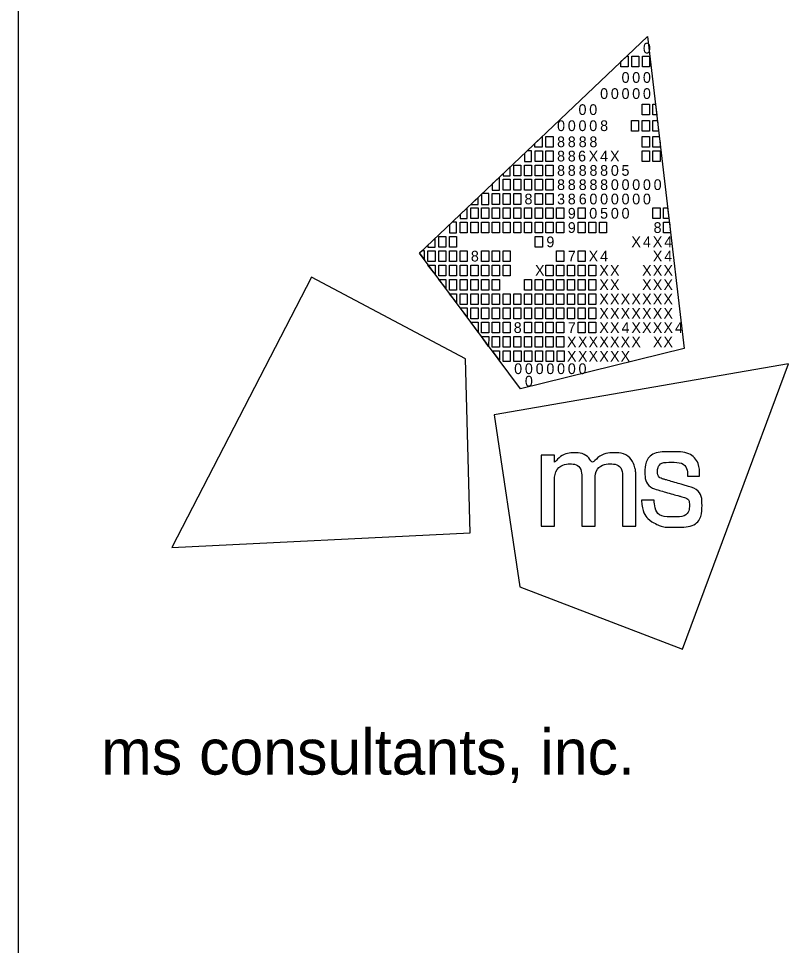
# Model space of a CAD drawing. Extents: x 0 to 34, y 0 to 22.
# Drawn here: x 32 to 33.186, y 2.686 to 4.114 of the extents above; entities that cross this region are included whole.
import ezdxf

# ---------------------------------------------------------------- set-up
doc = ezdxf.new("R2010")
doc.units = 0
doc.layers.add('SH_Border', color=7, linetype='Continuous')
doc.layers.add('SH_Data', color=7, linetype='Continuous')

msp = doc.modelspace()

# ---------------------------------------------------------------- linework, layer by layer
at = {"layer": 'SH_Border'}
msp.add_line((32, 0.5), (32, 21.5), dxfattribs=at)
at = {"layer": 'SH_Data'}
for p, q in [((32.6175, 3.7519), (32.9688, 4.0861)), ((32.9688, 4.0861), (32.9688, 4.0861)), ((32.9688, 4.0861), (33.0253, 3.6052)), ((32.773, 3.543), (32.6175, 3.7519)), ((33.0253, 3.6052), (32.773, 3.543)), ((32.75, 3.5), (32.75, 3.5))]:
    msp.add_line(p, q, dxfattribs=at)
for points in [[(32.9279, 4.0472), (32.9369, 4.0558), (32.9389, 4.0558), (32.9389, 4.0393), (32.9279, 4.0393)], [(32.9444, 4.0558), (32.9554, 4.0558), (32.9554, 4.0393), (32.9444, 4.0393)], [(32.9609, 4.0558), (32.9719, 4.0558), (32.9719, 4.0393), (32.9609, 4.0393)], [(32.9606, 3.9815), (32.9716, 3.9815), (32.9716, 3.965), (32.9606, 3.965)], [(32.9771, 3.9815), (32.9811, 3.9815), (32.983, 3.965), (32.9771, 3.965)], [(32.9441, 3.9567), (32.9551, 3.9567), (32.9551, 3.9402), (32.9441, 3.9402)], [(32.9606, 3.9567), (32.9716, 3.9567), (32.9716, 3.9402), (32.9606, 3.9402)], [(32.9771, 3.9567), (32.984, 3.9567), (32.9859, 3.9402), (32.9771, 3.9402)], [(32.7953, 3.9211), (32.8064, 3.9316), (32.8064, 3.9154), (32.7953, 3.9154)], [(32.8123, 3.9319), (32.8233, 3.9319), (32.8233, 3.9154), (32.8123, 3.9154)], [(32.9606, 3.9319), (32.9716, 3.9319), (32.9716, 3.9154), (32.9606, 3.9154)], [(32.9771, 3.9319), (32.9869, 3.9319), (32.9881, 3.9218), (32.9881, 3.9154), (32.9771, 3.9154)], [(32.7958, 3.9099), (32.8068, 3.9099), (32.8068, 3.8934), (32.7958, 3.8934)], [(32.8123, 3.9099), (32.8233, 3.9099), (32.8233, 3.8934), (32.8123, 3.8934)], [(32.9606, 3.9099), (32.9716, 3.9099), (32.9716, 3.8934), (32.9606, 3.8934)], [(32.9771, 3.9099), (32.9881, 3.9099), (32.9881, 3.8934), (32.9771, 3.8934)], [(32.7627, 3.8879), (32.7737, 3.8879), (32.7737, 3.8714), (32.7627, 3.8714)], [(32.7793, 3.8879), (32.7903, 3.8879), (32.7903, 3.8714), (32.7793, 3.8714)], [(32.7958, 3.8879), (32.8068, 3.8879), (32.8068, 3.8714), (32.7958, 3.8714)], [(32.8123, 3.8879), (32.8233, 3.8879), (32.8233, 3.8714), (32.8123, 3.8714)], [(32.7462, 3.8659), (32.7572, 3.8659), (32.7572, 3.8494), (32.7462, 3.8494)], [(32.7627, 3.8659), (32.7737, 3.8659), (32.7737, 3.8494), (32.7627, 3.8494)], [(32.7793, 3.8659), (32.7903, 3.8659), (32.7903, 3.8494), (32.7793, 3.8494)], [(32.7958, 3.8659), (32.8068, 3.8659), (32.8068, 3.8494), (32.7958, 3.8494)], [(32.8123, 3.8659), (32.8233, 3.8659), (32.8233, 3.8494), (32.8123, 3.8494)], [(32.7297, 3.8439), (32.7407, 3.8439), (32.7407, 3.8273), (32.7297, 3.8273)], [(32.7462, 3.8439), (32.7572, 3.8439), (32.7572, 3.8273), (32.7462, 3.8273)], [(32.7627, 3.8439), (32.7737, 3.8439), (32.7737, 3.8273), (32.7627, 3.8273)], [(32.7958, 3.8439), (32.8068, 3.8439), (32.8068, 3.8273), (32.7958, 3.8273)], [(32.8123, 3.8439), (32.8233, 3.8439), (32.8233, 3.8273), (32.8123, 3.8273)], [(32.6967, 3.8218), (32.7077, 3.8218), (32.7077, 3.8053), (32.6967, 3.8053)], [(32.7132, 3.8218), (32.7242, 3.8218), (32.7242, 3.8053), (32.7132, 3.8053)], [(32.7297, 3.8218), (32.7407, 3.8218), (32.7407, 3.8053), (32.7297, 3.8053)], [(32.7462, 3.8218), (32.7572, 3.8218), (32.7572, 3.8053), (32.7462, 3.8053)], [(32.7627, 3.8218), (32.7737, 3.8218), (32.7737, 3.8053), (32.7627, 3.8053)], [(32.7793, 3.8218), (32.7903, 3.8218), (32.7903, 3.8053), (32.7793, 3.8053)], [(32.7958, 3.8218), (32.8068, 3.8218), (32.8068, 3.8053), (32.7958, 3.8053)], [(32.8123, 3.8218), (32.8233, 3.8218), (32.8233, 3.8053), (32.8123, 3.8053)], [(32.8288, 3.8218), (32.8398, 3.8218), (32.8398, 3.8053), (32.8288, 3.8053)], [(32.8618, 3.8218), (32.8728, 3.8218), (32.8728, 3.8053), (32.8618, 3.8053)], [(32.9771, 3.8218), (32.9881, 3.8218), (32.9881, 3.8053), (32.9771, 3.8053)], [(32.9935, 3.8218), (32.9998, 3.8218), (33.0018, 3.8053), (32.9935, 3.8053)], [(32.6802, 3.7998), (32.6912, 3.7998), (32.6912, 3.7833), (32.6802, 3.7833)], [(32.6967, 3.7998), (32.7077, 3.7998), (32.7077, 3.7833), (32.6967, 3.7833)], [(32.7132, 3.7998), (32.7242, 3.7998), (32.7242, 3.7833), (32.7132, 3.7833)], [(32.7297, 3.7998), (32.7407, 3.7998), (32.7407, 3.7833), (32.7297, 3.7833)], [(32.7462, 3.7998), (32.7572, 3.7998), (32.7572, 3.7833), (32.7462, 3.7833)], [(32.7627, 3.7998), (32.7737, 3.7998), (32.7737, 3.7833), (32.7627, 3.7833)], [(32.7793, 3.7998), (32.7903, 3.7998), (32.7903, 3.7833), (32.7793, 3.7833)], [(32.7958, 3.7998), (32.8068, 3.7998), (32.8068, 3.7833), (32.7958, 3.7833)], [(32.8123, 3.7998), (32.8233, 3.7998), (32.8233, 3.7833), (32.8123, 3.7833)], [(32.8288, 3.7998), (32.8398, 3.7998), (32.8398, 3.7833), (32.8288, 3.7833)], [(32.8618, 3.7998), (32.8728, 3.7998), (32.8728, 3.7833), (32.8618, 3.7833)], [(32.8783, 3.7998), (32.8893, 3.7998), (32.8893, 3.7833), (32.8783, 3.7833)], [(32.8947, 3.7998), (32.9057, 3.7998), (32.9057, 3.7833), (32.8947, 3.7833)], [(32.9935, 3.7998), (33.0024, 3.7998), (33.0044, 3.7833), (32.9935, 3.7833)], [(32.6471, 3.7778), (32.6581, 3.7778), (32.6581, 3.7613), (32.6471, 3.7613)], [(32.6637, 3.7778), (32.6747, 3.7778), (32.6747, 3.7613), (32.6637, 3.7613)], [(32.7958, 3.7778), (32.8068, 3.7778), (32.8068, 3.7613), (32.7958, 3.7613)], [(32.6306, 3.7558), (32.6416, 3.7558), (32.6416, 3.7393), (32.6306, 3.7393)], [(32.6471, 3.7558), (32.6581, 3.7558), (32.6581, 3.7393), (32.6471, 3.7393)], [(32.6637, 3.7558), (32.6747, 3.7558), (32.6747, 3.7393), (32.6637, 3.7393)], [(32.6802, 3.7558), (32.6912, 3.7558), (32.6912, 3.7393), (32.6802, 3.7393)], [(32.7132, 3.7558), (32.7242, 3.7558), (32.7242, 3.7393), (32.7132, 3.7393)], [(32.7297, 3.7558), (32.7407, 3.7558), (32.7407, 3.7393), (32.7297, 3.7393)], [(32.7462, 3.7558), (32.7572, 3.7558), (32.7572, 3.7393), (32.7462, 3.7393)], [(32.8288, 3.7558), (32.8398, 3.7558), (32.8398, 3.7393), (32.8288, 3.7393)], [(32.8618, 3.7558), (32.8728, 3.7558), (32.8728, 3.7393), (32.8618, 3.7393)], [(32.6306, 3.7338), (32.6416, 3.7338), (32.6416, 3.72)], [(32.6471, 3.7338), (32.6581, 3.7338), (32.6581, 3.7173), (32.6471, 3.7173)], [(32.6637, 3.7338), (32.6747, 3.7338), (32.6747, 3.7173), (32.6637, 3.7173)], [(32.6802, 3.7338), (32.6912, 3.7338), (32.6912, 3.7173), (32.6802, 3.7173)], [(32.6967, 3.7338), (32.7077, 3.7338), (32.7077, 3.7173), (32.6967, 3.7173)], [(32.7132, 3.7338), (32.7242, 3.7338), (32.7242, 3.7173), (32.7132, 3.7173)], [(32.7297, 3.7338), (32.7407, 3.7338), (32.7407, 3.7173), (32.7297, 3.7173)], [(32.7462, 3.7338), (32.7572, 3.7338), (32.7572, 3.7173), (32.7462, 3.7173)], [(32.8123, 3.7338), (32.8233, 3.7338), (32.8233, 3.7173), (32.8123, 3.7173)], [(32.8288, 3.7338), (32.8398, 3.7338), (32.8398, 3.7173), (32.8288, 3.7173)], [(32.8453, 3.7338), (32.8563, 3.7338), (32.8563, 3.7173), (32.8453, 3.7173)], [(32.8618, 3.7338), (32.8728, 3.7338), (32.8728, 3.7173), (32.8618, 3.7173)], [(32.8783, 3.7338), (32.8893, 3.7338), (32.8893, 3.7173), (32.8783, 3.7173)], [(32.6471, 3.7117), (32.6581, 3.7117), (32.6581, 3.698)], [(32.6637, 3.7117), (32.6747, 3.7117), (32.6747, 3.6952), (32.6637, 3.6952)], [(32.6802, 3.7117), (32.6912, 3.7117), (32.6912, 3.6952), (32.6802, 3.6952)], [(32.6967, 3.7117), (32.7077, 3.7117), (32.7077, 3.6952), (32.6967, 3.6952)], [(32.7132, 3.7117), (32.7242, 3.7117), (32.7242, 3.6952), (32.7132, 3.6952)], [(32.7297, 3.7117), (32.7407, 3.7117), (32.7407, 3.6952), (32.7297, 3.6952)], [(32.7793, 3.7117), (32.7903, 3.7117), (32.7903, 3.6952), (32.7793, 3.6952)], [(32.7958, 3.7117), (32.8068, 3.7117), (32.8068, 3.6952), (32.7958, 3.6952)], [(32.8123, 3.7117), (32.8233, 3.7117), (32.8233, 3.6952), (32.8123, 3.6952)], [(32.8288, 3.7117), (32.8398, 3.7117), (32.8398, 3.6952), (32.8288, 3.6952)], [(32.8453, 3.7117), (32.8563, 3.7117), (32.8563, 3.6952), (32.8453, 3.6952)], [(32.8618, 3.7117), (32.8728, 3.7117), (32.8728, 3.6952), (32.8618, 3.6952)], [(32.8783, 3.7117), (32.8893, 3.7117), (32.8893, 3.6952), (32.8783, 3.6952)], [(32.6637, 3.6897), (32.6747, 3.6897), (32.6747, 3.676)], [(32.6747, 3.6897), (32.6747, 3.6897), (32.6747, 3.6897)], [(32.6802, 3.6897), (32.6912, 3.6897), (32.6912, 3.6732), (32.6802, 3.6732)], [(32.6967, 3.6897), (32.7077, 3.6897), (32.7077, 3.6732), (32.6967, 3.6732)], [(32.7132, 3.6897), (32.7242, 3.6897), (32.7242, 3.6732), (32.7132, 3.6732)], [(32.7297, 3.6897), (32.7407, 3.6897), (32.7407, 3.6732), (32.7297, 3.6732)], [(32.7462, 3.6897), (32.7572, 3.6897), (32.7572, 3.6732), (32.7462, 3.6732)], [(32.7627, 3.6897), (32.7737, 3.6897), (32.7737, 3.6732), (32.7627, 3.6732)], [(32.7793, 3.6897), (32.7903, 3.6897), (32.7903, 3.6732), (32.7793, 3.6732)], [(32.7958, 3.6897), (32.8068, 3.6897), (32.8068, 3.6732), (32.7958, 3.6732)], [(32.8123, 3.6897), (32.8233, 3.6897), (32.8233, 3.6732), (32.8123, 3.6732)], [(32.8288, 3.6897), (32.8398, 3.6897), (32.8398, 3.6732), (32.8288, 3.6732)], [(32.8453, 3.6897), (32.8563, 3.6897), (32.8563, 3.6732), (32.8453, 3.6732)], [(32.8618, 3.6897), (32.8728, 3.6897), (32.8728, 3.6732), (32.8618, 3.6732)], [(32.8783, 3.6897), (32.8893, 3.6897), (32.8893, 3.6732), (32.8783, 3.6732)], [(32.6802, 3.6677), (32.6912, 3.6677), (32.6912, 3.654)], [(32.6967, 3.6677), (32.7077, 3.6677), (32.7077, 3.6512), (32.6967, 3.6512)], [(32.7132, 3.6677), (32.7242, 3.6677), (32.7242, 3.6512), (32.7132, 3.6512)], [(32.7297, 3.6677), (32.7407, 3.6677), (32.7407, 3.6512), (32.7297, 3.6512)], [(32.7462, 3.6677), (32.7572, 3.6677), (32.7572, 3.6512), (32.7462, 3.6512)], [(32.7627, 3.6677), (32.7737, 3.6677), (32.7737, 3.6512), (32.7627, 3.6512)], [(32.7793, 3.6677), (32.7903, 3.6677), (32.7903, 3.6512), (32.7793, 3.6512)], [(32.7958, 3.6677), (32.8068, 3.6677), (32.8068, 3.6512), (32.7958, 3.6512)], [(32.8123, 3.6677), (32.8233, 3.6677), (32.8233, 3.6512), (32.8123, 3.6512)], [(32.8288, 3.6677), (32.8398, 3.6677), (32.8398, 3.6512), (32.8288, 3.6512)], [(32.8453, 3.6677), (32.8563, 3.6677), (32.8563, 3.6512), (32.8453, 3.6512)], [(32.8618, 3.6677), (32.8728, 3.6677), (32.8728, 3.6512), (32.8618, 3.6512)], [(32.8783, 3.6677), (32.8893, 3.6677), (32.8893, 3.6512), (32.8783, 3.6512)], [(32.7077, 3.6305), (32.6965, 3.6457), (32.7077, 3.6457)], [(32.7132, 3.6457), (32.7242, 3.6457), (32.7242, 3.6292), (32.7132, 3.6292)], [(32.7297, 3.6457), (32.7407, 3.6457), (32.7407, 3.6292), (32.7297, 3.6292)], [(32.7462, 3.6457), (32.7572, 3.6457), (32.7572, 3.6292), (32.7462, 3.6292)], [(32.7793, 3.6457), (32.7903, 3.6457), (32.7903, 3.6292), (32.7793, 3.6292)], [(32.7958, 3.6457), (32.8068, 3.6457), (32.8068, 3.6292), (32.7958, 3.6292)], [(32.8123, 3.6457), (32.8233, 3.6457), (32.8233, 3.6292), (32.8123, 3.6292)], [(32.8288, 3.6457), (32.8398, 3.6457), (32.8398, 3.6292), (32.8288, 3.6292)], [(32.8618, 3.6457), (32.8728, 3.6457), (32.8728, 3.6292), (32.8618, 3.6292)], [(32.8783, 3.6457), (32.8893, 3.6457), (32.8893, 3.6292), (32.8783, 3.6292)], [(32.724, 3.6082), (32.7132, 3.6237), (32.7242, 3.6237)], [(32.7297, 3.6237), (32.7407, 3.6237), (32.7407, 3.6072), (32.7297, 3.6072)], [(32.7462, 3.6237), (32.7572, 3.6237), (32.7572, 3.6072), (32.7462, 3.6072)], [(32.7627, 3.6237), (32.7737, 3.6237), (32.7737, 3.6072), (32.7627, 3.6072)], [(32.7793, 3.6237), (32.7903, 3.6237), (32.7903, 3.6072), (32.7793, 3.6072)], [(32.7958, 3.6237), (32.8068, 3.6237), (32.8068, 3.6072), (32.7958, 3.6072)], [(32.8123, 3.6237), (32.8233, 3.6237), (32.8233, 3.6072), (32.8123, 3.6072)], [(32.8288, 3.6237), (32.8398, 3.6237), (32.8398, 3.6072), (32.8288, 3.6072)], [(32.7302, 3.6017), (32.7407, 3.6017), (32.7408, 3.5875)], [(32.7463, 3.6017), (32.7573, 3.6017), (32.7573, 3.5852), (32.7463, 3.5852)], [(32.763, 3.6017), (32.774, 3.6017), (32.774, 3.5852), (32.763, 3.5852)], [(32.7794, 3.6017), (32.7904, 3.6017), (32.7904, 3.5852), (32.7794, 3.5852)], [(32.796, 3.6017), (32.807, 3.6017), (32.807, 3.5852), (32.796, 3.5852)], [(32.8129, 3.6017), (32.8239, 3.6017), (32.8239, 3.5851), (32.8129, 3.5851)], [(32.8296, 3.6017), (32.8406, 3.6017), (32.8406, 3.5851), (32.8296, 3.5851)]]:
    msp.add_lwpolyline(points, close=True, dxfattribs=at)
for points in [[(32.7903, 3.9099), (32.7836, 3.9099), (32.7793, 3.9058), (32.7793, 3.8934), (32.7903, 3.8934), (32.7903, 3.9099)], [(32.7572, 3.8849), (32.7462, 3.8744), (32.7462, 3.8714), (32.7572, 3.8714), (32.7572, 3.8849)], [(32.7407, 3.8691), (32.7297, 3.8587), (32.7297, 3.8494), (32.7407, 3.8494), (32.7407, 3.8691)], [(32.7242, 3.8439), (32.7141, 3.8439), (32.7132, 3.843), (32.7132, 3.8273), (32.7242, 3.8273), (32.7242, 3.8439)], [(32.7077, 3.8377), (32.6968, 3.8273), (32.7077, 3.8273), (32.7077, 3.8377)], [(32.6912, 3.822), (32.6802, 3.8115), (32.6802, 3.8053), (32.6912, 3.8053), (32.6912, 3.822)], [(32.6747, 3.7998), (32.6679, 3.7998), (32.6637, 3.7958), (32.6637, 3.7833), (32.6747, 3.7833), (32.6747, 3.7998)], [(32.6416, 3.7749), (32.6306, 3.7644), (32.6306, 3.7613), (32.6416, 3.7613), (32.6416, 3.7749)], [(32.6251, 3.7558), (32.6216, 3.7558), (32.6175, 3.7519), (32.6251, 3.7417), (32.6251, 3.7558)], [(32.4512, 3.7149), (32.2359, 3.2988), (32.6956, 3.3215), (32.6884, 3.5892), (32.4512, 3.7149)], [(33.0229, 3.1422), (33.1859, 3.5814), (32.7324, 3.5029), (32.7722, 3.2381), (33.0229, 3.1422)]]:
    msp.add_lwpolyline(points, dxfattribs=at)
for points in [[(32.8048, 3.3315), (32.8048, 3.3315), (32.8048, 3.4409), (32.8048, 3.4409), (32.8048, 3.4409), (32.8255, 3.4409), (32.8255, 3.4409), (32.8255, 3.4409), (32.8255, 3.4297), (32.8255, 3.4297), (32.8346, 3.4399), (32.8457, 3.4445), (32.8555, 3.4445), (32.8688, 3.4445), (32.8791, 3.4372), (32.8837, 3.4266), (32.8915, 3.4381), (32.905, 3.4446), (32.9166, 3.4446), (32.9325, 3.4446), (32.9451, 3.435), (32.9494, 3.4213), (32.9494, 3.4212), (32.9494, 3.4212), (32.9494, 3.4212), (32.9501, 3.419), (32.9506, 3.4172), (32.9506, 3.4071), (32.9506, 3.4071), (32.9506, 3.3314), (32.9506, 3.3314), (32.9506, 3.3314), (32.9303, 3.3314), (32.9303, 3.3314), (32.9303, 3.3314), (32.9303, 3.4048), (32.9303, 3.4048), (32.9303, 3.4201), (32.9219, 3.4274), (32.911, 3.4274), (32.8995, 3.4274), (32.8879, 3.4171), (32.8879, 3.4001), (32.8879, 3.4001), (32.8879, 3.3315), (32.8879, 3.3315), (32.8879, 3.3315), (32.8674, 3.3315), (32.8674, 3.3315), (32.8674, 3.3315), (32.8674, 3.4059), (32.8674, 3.4059), (32.8674, 3.4203), (32.8588, 3.4274), (32.8496, 3.4274), (32.8384, 3.4274), (32.8254, 3.417), (32.8254, 3.3962), (32.8254, 3.3962), (32.8254, 3.3315), (32.8254, 3.3315), (32.8254, 3.3315), (32.8048, 3.3315), (32.8048, 3.3315)], [(32.9595, 3.3709), (32.9595, 3.3709), (32.9595, 3.3717), (32.9595, 3.3717), (32.9595, 3.3717), (32.9603, 3.3717), (32.9603, 3.3717), (32.9603, 3.3717), (32.9783, 3.3717), (32.9783, 3.3717), (32.9783, 3.3717), (32.9789, 3.3717), (32.9789, 3.3717), (32.9789, 3.3717), (32.979, 3.371), (32.979, 3.371), (32.9803, 3.3554), (32.9887, 3.346), (33.009, 3.346), (33.0273, 3.346), (33.0333, 3.3554), (33.0333, 3.3631), (33.0333, 3.3732), (33.0256, 3.3758), (33.0175, 3.378), (33.0175, 3.378), (32.987, 3.3867), (32.987, 3.3867), (32.972, 3.3909), (32.9648, 3.4019), (32.9648, 3.4142), (32.9648, 3.4303), (32.9768, 3.4462), (33.0052, 3.4462), (33.0348, 3.4462), (33.0489, 3.4285), (33.0489, 3.4095), (33.0489, 3.4095), (33.0489, 3.4087), (33.0489, 3.4087), (33.0489, 3.4087), (33.0482, 3.4087), (33.0482, 3.4087), (33.0482, 3.4087), (33.0312, 3.4087), (33.0312, 3.4087), (33.0312, 3.4087), (33.0305, 3.4087), (33.0305, 3.4087), (33.0305, 3.4087), (33.0305, 3.4094), (33.0305, 3.4094), (33.0301, 3.4208), (33.0226, 3.43), (33.0056, 3.43), (32.9891, 3.43), (32.9843, 3.4218), (32.9843, 3.4157), (32.9843, 3.4108), (32.9869, 3.4059), (32.9959, 3.4033), (32.9959, 3.4033), (33.0255, 3.3948), (33.0255, 3.3948), (33.0462, 3.3889), (33.0527, 3.3777), (33.0527, 3.3639), (33.0527, 3.3462), (33.041, 3.3298), (33.0087, 3.3298), (32.9952, 3.3298), (32.9877, 3.3321), (32.9823, 3.3348), (32.969, 3.3414), (32.9609, 3.3536), (32.9595, 3.3709)]]:
    msp.add_open_spline(points, degree=3, dxfattribs=at)

# ---------------------------------------------------------------- texts
for s, height, p in [('0', 0.0165, (32.9617, 4.0597)), ('0', 0.0165, (32.9288, 4.0145)), ('0', 0.0165, (32.9452, 4.0145)), ('0', 0.0165, (32.9617, 4.0145)), ('0', 0.0165, (32.8958, 3.9897)), ('0', 0.0165, (32.9123, 3.9897)), ('0', 0.0165, (32.9288, 3.9897)), ('0', 0.0165, (32.9452, 3.9897)), ('0', 0.0165, (32.9617, 3.9897)), ('0', 0.0165, (32.8625, 3.965)), ('0', 0.0165, (32.879, 3.965)), ('0', 0.0165, (32.8295, 3.9402)), ('0', 0.0165, (32.846, 3.9402)), ('0', 0.0165, (32.8625, 3.9402)), ('0', 0.0165, (32.879, 3.9402)), ('8', 0.0165, (32.8958, 3.9402)), ('8', 0.0165, (32.8295, 3.9154)), ('8', 0.0165, (32.846, 3.9154)), ('8', 0.0165, (32.8628, 3.9154)), ('8', 0.0165, (32.8793, 3.9154)), ('8', 0.0165, (32.8295, 3.8934)), ('8', 0.0165, (32.846, 3.8934)), ('6', 0.0165, (32.8618, 3.8934)), ('X', 0.0165, (32.8781, 3.8934)), ('4', 0.0165, (32.8958, 3.8934)), ('X', 0.0165, (32.911, 3.8934)), ('8', 0.0165, (32.8295, 3.8713)), ('8', 0.0165, (32.846, 3.8713)), ('8', 0.0165, (32.8628, 3.8713)), ('8', 0.0165, (32.8794, 3.8713)), ('8', 0.0165, (32.8958, 3.8713)), ('0', 0.0165, (32.9123, 3.8713)), ('5', 0.0165, (32.9287, 3.8713)), ('8', 0.0165, (32.8295, 3.8494)), ('8', 0.0165, (32.846, 3.8494)), ('8', 0.0165, (32.8628, 3.8494)), ('8', 0.0165, (32.8794, 3.8494)), ('8', 0.0165, (32.8958, 3.8494)), ('0', 0.0165, (32.9123, 3.8494)), ('0', 0.0165, (32.9288, 3.8494)), ('0', 0.0165, (32.9452, 3.8494)), ('0', 0.0165, (32.9617, 3.8494)), ('0', 0.0165, (32.9782, 3.8494)), ('8', 0.0165, (32.7793, 3.8273)), ('3', 0.0165, (32.8295, 3.8273)), ('8', 0.0165, (32.846, 3.8273)), ('6', 0.0165, (32.8629, 3.8273)), ('0', 0.0165, (32.8793, 3.8273)), ('0', 0.0165, (32.8958, 3.8273)), ('0', 0.0165, (32.9123, 3.8273)), ('0', 0.0165, (32.9288, 3.8273)), ('0', 0.0165, (32.9452, 3.8273)), ('0', 0.0165, (32.9617, 3.8273)), ('9', 0.0165, (32.846, 3.8053)), ('0', 0.0165, (32.879, 3.8053)), ('5', 0.0165, (32.8957, 3.8053)), ('0', 0.0165, (32.9123, 3.8053)), ('0', 0.0165, (32.9288, 3.8053)), ('9', 0.0165, (32.846, 3.7833)), ('8', 0.0165, (32.9781, 3.7833)), ('9', 0.0165, (32.813, 3.7613)), ('X', 0.0165, (32.9439, 3.7613)), ('4', 0.0165, (32.9617, 3.7613)), ('X', 0.0165, (32.9769, 3.7613)), ('4', 0.0165, (32.9946, 3.7613)), ('8', 0.0165, (32.6967, 3.7393)), ('7', 0.0165, (32.846, 3.7393)), ('X', 0.0165, (32.8781, 3.7393)), ('4', 0.0165, (32.8958, 3.7393)), ('X', 0.0165, (32.9769, 3.7393)), ('4', 0.0165, (32.9946, 3.7393)), ('X', 0.0165, (32.7955, 3.7173)), ('X', 0.0165, (32.8945, 3.7173)), ('X', 0.0165, (32.911, 3.7173)), ('X', 0.0165, (32.9604, 3.7173)), ('X', 0.0165, (32.9769, 3.7173)), ('X', 0.0165, (32.9933, 3.7173)), ('X', 0.0165, (32.8945, 3.6952)), ('X', 0.0165, (32.911, 3.6952)), ('X', 0.0165, (32.9604, 3.6952)), ('X', 0.0165, (32.9769, 3.6952)), ('X', 0.0165, (32.9933, 3.6952)), ('X', 0.0165, (32.8945, 3.6732)), ('X', 0.0165, (32.911, 3.6732)), ('X', 0.0165, (32.9274, 3.6732)), ('X', 0.0165, (32.9439, 3.6732)), ('X', 0.0165, (32.9604, 3.6732)), ('X', 0.0165, (32.9769, 3.6732)), ('X', 0.0165, (32.9933, 3.6732)), ('X', 0.0165, (32.8945, 3.6512)), ('X', 0.0165, (32.911, 3.6512)), ('X', 0.0165, (32.9274, 3.6512)), ('X', 0.0165, (32.9439, 3.6512)), ('X', 0.0165, (32.9604, 3.6512)), ('X', 0.0165, (32.9769, 3.6512)), ('X', 0.0165, (32.9933, 3.6512)), ('8', 0.0165, (32.7627, 3.6292)), ('7', 0.0165, (32.846, 3.6292)), ('X', 0.0165, (32.8945, 3.6292)), ('X', 0.0165, (32.911, 3.6292)), ('4', 0.0165, (32.9288, 3.6292)), ('X', 0.0165, (32.9439, 3.6292)), ('X', 0.0165, (32.9604, 3.6292)), ('X', 0.0165, (32.9769, 3.6292)), ('X', 0.0165, (32.9933, 3.6292)), ('4', 0.0165, (33.0111, 3.6292)), ('X', 0.0165, (32.8447, 3.6072)), ('X', 0.0165, (32.8616, 3.6072)), ('X', 0.0165, (32.878, 3.6072)), ('X', 0.0165, (32.8945, 3.6072)), ('X', 0.0165, (32.911, 3.6072)), ('X', 0.0165, (32.9274, 3.6072)), ('X', 0.0165, (32.9439, 3.6072)), ('X', 0.0165, (32.9771, 3.6072)), ('X', 0.0165, (32.9933, 3.6072)), ('X', 0.0165, (32.8447, 3.5851)), ('X', 0.0165, (32.8616, 3.5851)), ('X', 0.0165, (32.878, 3.5851)), ('X', 0.0165, (32.8945, 3.5851)), ('X', 0.0165, (32.911, 3.5851)), ('X', 0.0165, (32.9274, 3.5851)), ('0', 0.0165, (32.7634, 3.5659)), ('0', 0.0165, (32.7799, 3.5659)), ('0', 0.0165, (32.7965, 3.5659)), ('0', 0.0165, (32.813, 3.5659)), ('0', 0.0165, (32.8295, 3.5659)), ('0', 0.0165, (32.846, 3.5659)), ('0', 0.0165, (32.8625, 3.5659)), ('0', 0.0165, (32.7799, 3.5467)), ('ms consultants, inc.', 0.07, (32.1273, 2.9489))]:
    msp.add_text(s, height=height, rotation=360, dxfattribs=at).set_placement(p)

doc.saveas('drawing.dxf')
